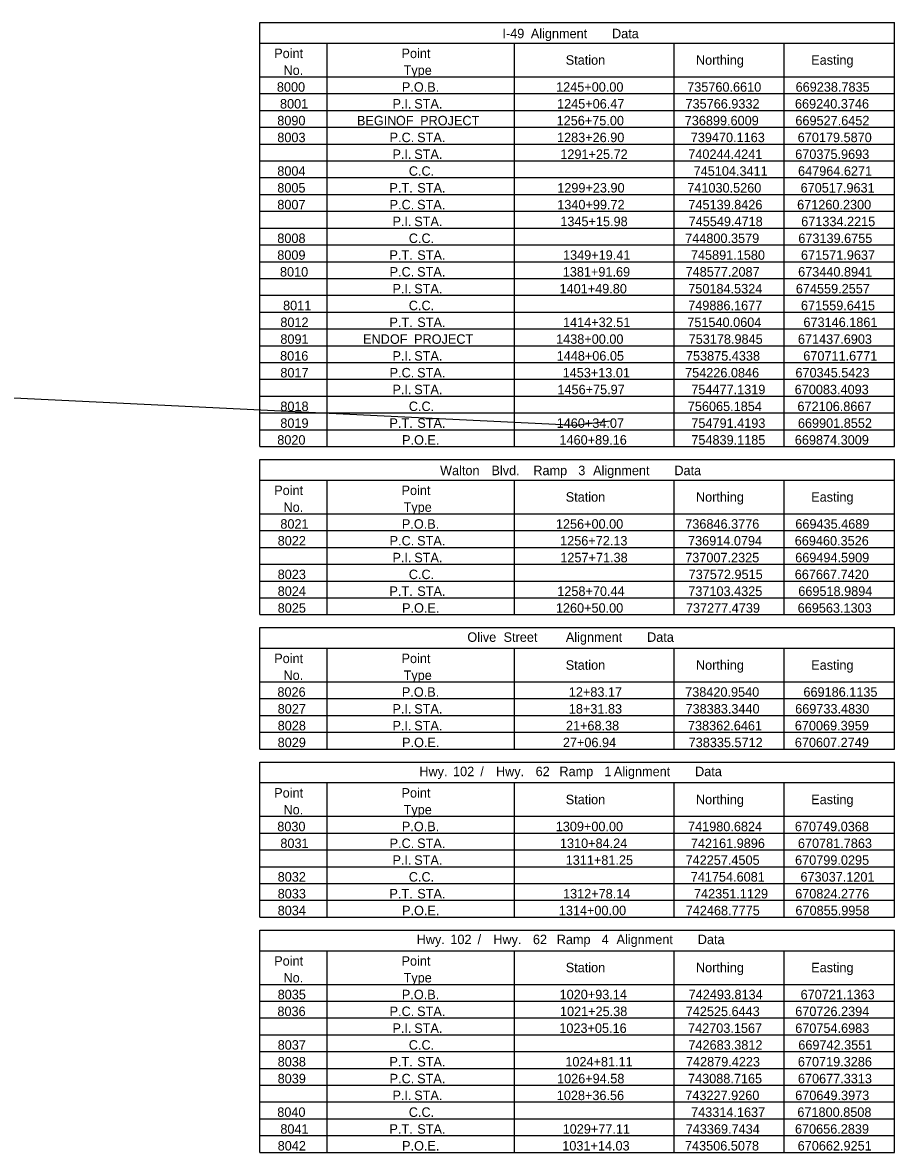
# Model space of a CAD drawing. Extents: x 672566 to 676329, y 739687 to 740710.
# Drawn here: x 673612 to 674071, y 739910 to 740505 of the extents above; entities that cross this region are included whole.
import ezdxf

# ---------------------------------------------------------------- set-up
doc = ezdxf.new("R2010")
doc.units = 0
doc.layers.add('R_Border', color=7, linetype='Continuous')
doc.layers.add('S_BASELINE', color=7, linetype='Continuous')

msp = doc.modelspace()

# ---------------------------------------------------------------- linework, layer by layer
at = {"layer": 'R_Border'}
msp.add_lwpolyline([(673921.66, 740294.96), (673903.74, 740292.61), (672625.13, 740354.75)], dxfattribs=at)
at = {"layer": 'S_BASELINE'}
for p, q in [((673737.18, 740504.83), (674071.38, 740504.83)), ((673737.18, 740281.51), (673737.18, 740504.83)), ((674071.38, 740281.51), (674071.38, 740504.83)), ((673737.18, 740502.83), (673737.18, 740502.83)), ((673737.18, 740493.98), (674071.38, 740493.98)), ((673772.59, 740281.51), (673772.59, 740493.98)), ((673871.3, 740281.51), (673871.3, 740493.98)), ((673955.4, 740281.51), (673955.4, 740493.98)), ((674013.39, 740281.51), (674013.39, 740493.98)), ((673737.18, 740476.27), (674071.38, 740476.27)), ((673737.18, 740476.27), (673772.59, 740476.27)), ((673737.18, 740467.42), (674071.38, 740467.42)), ((673737.18, 740458.57), (674071.38, 740458.57)), ((673737.18, 740449.72), (674071.38, 740449.72)), ((673737.18, 740440.86), (674071.38, 740440.86)), ((673737.18, 740432.01), (674071.38, 740432.01)), ((673737.18, 740423.16), (674071.38, 740423.16)), ((673737.18, 740414.3), (674071.38, 740414.3)), ((673737.18, 740405.45), (674071.38, 740405.45)), ((673737.18, 740396.6), (674071.38, 740396.6)), ((673737.18, 740387.74), (674071.38, 740387.74)), ((673737.18, 740378.89), (674071.38, 740378.89)), ((673737.18, 740370.04), (674071.38, 740370.04)), ((673737.18, 740361.19), (674071.38, 740361.19)), ((673737.18, 740352.33), (674071.38, 740352.33)), ((673737.18, 740343.48), (674071.38, 740343.48)), ((673737.18, 740334.63), (674071.38, 740334.63)), ((673737.18, 740325.77), (674071.38, 740325.77)), ((673737.18, 740316.92), (674071.38, 740316.92)), ((673737.18, 740308.07), (674071.38, 740308.07)), ((673737.18, 740299.21), (674071.38, 740299.21)), ((673737.18, 740290.36), (674071.38, 740290.36)), ((673737.18, 740281.51), (674071.38, 740281.51)), ((673737.18, 740274.66), (674071.38, 740274.66)), ((673737.18, 740192.98), (673737.18, 740274.66)), ((674071.38, 740192.98), (674071.38, 740274.66)), ((673737.18, 740263.8), (674071.38, 740263.8)), ((673772.59, 740192.98), (673772.59, 740263.8)), ((673871.3, 740192.98), (673871.3, 740263.8)), ((673955.4, 740192.98), (673955.4, 740263.8)), ((674013.39, 740192.98), (674013.39, 740263.8)), ((673737.18, 740246.1), (674071.38, 740246.1)), ((673737.18, 740246.1), (673772.59, 740246.1)), ((673737.18, 740237.24), (674071.38, 740237.24)), ((673737.18, 740228.39), (674071.38, 740228.39)), ((673737.18, 740219.54), (674071.38, 740219.54)), ((673737.18, 740210.68), (674071.38, 740210.68)), ((673737.18, 740201.83), (674071.38, 740201.83)), ((673737.18, 740192.98), (674071.38, 740192.98)), ((673737.18, 740186.13), (674071.38, 740186.13)), ((673737.18, 740122.15), (673737.18, 740186.13)), ((674071.38, 740122.15), (674071.38, 740186.13)), ((673737.18, 740175.27), (674071.38, 740175.27)), ((673772.59, 740122.15), (673772.59, 740175.27)), ((673871.3, 740122.15), (673871.3, 740175.27)), ((673955.4, 740122.15), (673955.4, 740175.27)), ((674013.39, 740122.15), (674013.39, 740175.27)), ((673737.18, 740157.57), (674071.38, 740157.57)), ((673737.18, 740157.57), (673772.59, 740157.57)), ((673737.18, 740148.71), (674071.38, 740148.71)), ((673737.18, 740139.86), (674071.38, 740139.86)), ((673737.18, 740131.01), (674071.38, 740131.01)), ((673737.18, 740122.15), (674071.38, 740122.15)), ((673737.18, 740115.3), (674071.38, 740115.3)), ((673737.18, 740033.62), (673737.18, 740115.3)), ((674071.38, 740033.62), (674071.38, 740115.3)), ((673737.18, 740104.45), (674071.38, 740104.45)), ((673772.59, 740033.62), (673772.59, 740104.45)), ((673871.3, 740033.62), (673871.3, 740104.45)), ((673955.4, 740033.62), (673955.4, 740104.45)), ((674013.39, 740033.62), (674013.39, 740104.45)), ((673737.18, 740086.74), (674071.38, 740086.74)), ((673737.18, 740086.74), (673772.59, 740086.74)), ((673737.18, 740077.89), (674071.38, 740077.89)), ((673737.18, 740069.04), (674071.38, 740069.04)), ((673737.18, 740060.18), (674071.38, 740060.18)), ((673737.18, 740051.33), (674071.38, 740051.33)), ((673737.18, 740042.48), (674071.38, 740042.48)), ((673737.18, 740033.62), (674071.38, 740033.62)), ((673737.18, 740026.77), (674071.38, 740026.77)), ((673737.18, 739909.68), (673737.18, 740026.77)), ((673737.18, 740024.77), (673737.18, 740024.77)), ((674071.38, 739909.68), (674071.38, 740026.77)), ((673737.18, 740015.92), (674071.38, 740015.92)), ((673772.59, 739909.68), (673772.59, 740015.92)), ((673871.3, 739909.68), (673871.3, 740015.92)), ((673955.4, 739909.68), (673955.4, 740015.92)), ((674013.39, 739909.68), (674013.39, 740015.92)), ((673737.18, 739998.21), (674071.38, 739998.21)), ((673737.18, 739998.21), (673772.59, 739998.21)), ((673737.18, 739989.36), (674071.38, 739989.36)), ((673737.18, 739980.51), (674071.38, 739980.51)), ((673737.18, 739971.65), (674071.38, 739971.65)), ((673737.18, 739962.8), (674071.38, 739962.8)), ((673737.18, 739953.95), (674071.38, 739953.95)), ((673737.18, 739945.09), (674071.38, 739945.09)), ((673737.18, 739936.24), (674071.38, 739936.24)), ((673737.18, 739927.39), (674071.38, 739927.39)), ((673737.18, 739918.54), (674071.38, 739918.54)), ((673737.18, 739909.68), (674071.38, 739909.68))]:
    msp.add_line(p, q, dxfattribs=at)

# ---------------------------------------------------------------- texts
for s, p in [('I-49', (673864.92, 740496.59)), (' Alignment', (673878.01, 740496.59)), (' Data', (673920.79, 740496.59)), ('Point', (673744.72, 740486.13)), ('Point', (673811.78, 740486.13)), ('Station', (673898.27, 740482.63)), ('Northing', (673966.86, 740482.63)), ('Easting', (674027.56, 740482.63)), ('No.', (673749.61, 740477.27)), ('Type', (673812.86, 740477.27)), ('8000', (673746.13, 740468.42)), ('P.O.B.', (673811.96, 740468.42)), ('1245+00.00', (673893.2, 740468.42)), ('735760.6610', (673962.24, 740468.42)), ('669238.7835', (674019.34, 740468.42)), ('8001', (673747.77, 740459.57)), ('P.I.', (673807.02, 740459.57)), (' STA.', (673816.62, 740459.57)), ('1245+06.47', (673893.69, 740459.57)), ('735766.9332', (673961.35, 740459.57)), ('669240.3746', (674019.01, 740459.57)), ('8090', (673746.33, 740450.71)), ('BEGIN', (673788.3, 740450.71)), (' OF', (673806.98, 740450.71)), (' PROJECT', (673819.72, 740450.71)), ('1256+75.00', (673893.47, 740450.71)), ('736899.6009', (673960.94, 740450.71)), ('669527.6452', (674019.22, 740450.71)), ('8003', (673746.35, 740441.86)), ('P.C.', (673805.49, 740441.86)), (' STA.', (673818.15, 740441.86)), ('1283+26.90', (673893.67, 740441.86)), ('739470.1163', (673964.11, 740441.86)), ('670179.5870', (674020.46, 740441.86)), ('P.I.', (673807.02, 740433.01)), (' STA.', (673816.62, 740433.01)), ('1291+25.72', (673895.42, 740433.01)), ('740244.4241', (673962.81, 740433.01)), ('670375.9693', (674019.14, 740433.01)), ('8004', (673746.35, 740424.15)), ('C.C.', (673815.61, 740424.15)), ('745104.3411', (673965.64, 740424.15)), ('647964.6271', (674020.64, 740424.15)), ('8005', (673746.35, 740415.3)), ('P.T.', (673805.41, 740415.3)), (' STA.', (673818.23, 740415.3)), ('1299+23.90', (673893.79, 740415.3)), ('741030.5260', (673962.28, 740415.3)), ('670517.9631', (674021.98, 740415.3)), ('8007', (673746.35, 740406.45)), ('P.C.', (673805.49, 740406.45)), (' STA.', (673818.15, 740406.45)), ('1340+99.72', (673893.81, 740406.45)), ('745139.8426', (673962.87, 740406.45)), ('671260.2300', (674020.15, 740406.45)), ('P.I.', (673807.02, 740397.6)), (' STA.', (673816.62, 740397.6)), ('1345+15.98', (673895.42, 740397.6)), ('745549.4718', (673963.01, 740397.6)), ('671334.2215', (674022.29, 740397.6)), ('8008', (673746.35, 740388.74)), ('C.C.', (673815.61, 740388.74)), ('744800.3579', (673961.18, 740388.74)), ('673139.6755', (674020.76, 740388.74)), ('8009', (673746.33, 740379.89)), ('P.T.', (673805.41, 740379.89)), (' STA.', (673818.23, 740379.89)), ('1349+19.41', (673896.84, 740379.89)), ('745891.1580', (673964.2, 740379.89)), ('671571.9637', (674022.17, 740379.89)), ('8010', (673747.75, 740371.04)), ('P.C.', (673805.49, 740371.04)), (' STA.', (673818.15, 740371.04)), ('1381+91.69', (673896.7, 740371.04)), ('748577.2087', (673961.39, 740371.04)), ('673440.8941', (674020.68, 740371.04)), ('P.I.', (673807.02, 740362.18)), (' STA.', (673816.62, 740362.18)), ('1401+49.80', (673895.01, 740362.18)), ('750184.5324', (673962.81, 740362.18)), ('674559.2557', (674019.46, 740362.18)), ('8011', (673749.38, 740353.33)), ('C.C.', (673815.61, 740353.33)), ('749886.1677', (673962.77, 740353.33)), ('671559.6415', (674022.17, 740353.33)), ('8012', (673747.96, 740344.48)), ('P.T.', (673805.41, 740344.48)), (' STA.', (673818.23, 740344.48)), ('1414+32.51', (673896.84, 740344.48)), ('751540.0604', (673962.3, 740344.48)), ('673146.1861', (674023.47, 740344.48)), ('8091', (673747.96, 740335.62)), ('END', (673791.49, 740335.62)), (' OF', (673803.8, 740335.62)), (' PROJECT', (673816.54, 740335.62)), ('1438+00.00', (673893.2, 740335.62)), ('753178.9845', (673963.01, 740335.62)), ('671437.6903', (674020.56, 740335.62)), ('8016', (673747.82, 740326.77)), ('P.I.', (673807.02, 740326.77)), (' STA.', (673816.62, 740326.77)), ('1448+06.05', (673893.49, 740326.77)), ('753875.4338', (673961.59, 740326.77)), ('670711.6771', (674023.39, 740326.77)), ('8017', (673747.96, 740317.92)), ('P.C.', (673805.49, 740317.92)), (' STA.', (673818.15, 740317.92)), ('1453+13.01', (673896.64, 740317.92)), ('754226.0846', (673961.14, 740317.92)), ('670345.5423', (674019.26, 740317.92)), ('P.I.', (673807.02, 740309.07)), (' STA.', (673816.62, 740309.07)), ('1456+75.97', (673893.89, 740309.07)), ('754477.1319', (673964.4, 740309.07)), ('670083.4093', (674018.87, 740309.07)), ('8018', (673747.96, 740300.21)), ('C.C.', (673815.61, 740300.21)), ('756065.1854', (673962.57, 740300.21)), ('672106.8667', (674020.32, 740300.21)), ('8019', (673747.94, 740291.36)), (' STA.', (673818.23, 740291.36)), ('1460+34.07', (673893.49, 740291.36)), ('754791.4193', (673964.42, 740291.36)), ('669901.8552', (674020.56, 740291.36)), ('P.T.', (673805.41, 740291.36)), ('8020', (673746.33, 740282.51)), ('P.O.E.', (673812.07, 740282.51)), ('1460+89.16', (673894.97, 740282.51)), ('754839.1185', (673964.42, 740282.51)), ('669874.3009', (674018.93, 740282.51)), ('Walton', (673832.08, 740266.42)), (' Blvd.', (673857.29, 740266.42)), (' Ramp', (673879.35, 740266.42)), (' 3', (673903.02, 740266.42)), (' Alignment', (673910.84, 740266.42)), (' Data', (673953.63, 740266.42)), ('Point', (673744.72, 740255.95)), ('Point', (673811.78, 740255.95)), ('Station', (673898.27, 740252.45)), ('Northing', (673966.86, 740252.45)), ('Easting', (674027.56, 740252.45)), ('No.', (673749.61, 740247.09)), ('Type', (673812.86, 740247.09)), ('8021', (673747.96, 740238.24)), ('P.O.B.', (673811.96, 740238.24)), ('1256+00.00', (673893.08, 740238.24)), ('736846.3776', (673961.22, 740238.24)), ('669435.4689', (674019.2, 740238.24)), ('8022', (673746.55, 740229.39)), ('P.C.', (673805.49, 740229.39)), (' STA.', (673818.15, 740229.39)), ('1256+72.13', (673895.3, 740229.39)), ('736914.0794', (673962.69, 740229.39)), ('669460.3526', (674018.89, 740229.39)), ('P.I.', (673807.02, 740220.54)), (' STA.', (673816.62, 740220.54)), ('1257+71.38', (673895.42, 740220.54)), ('737007.2325', (673961.2, 740220.54)), ('669494.5909', (674019.12, 740220.54)), ('8023', (673746.55, 740211.68)), ('C.C.', (673815.61, 740211.68)), ('737572.9515', (673963.01, 740211.68)), ('667667.7420', (674018.89, 740211.68)), ('8024', (673746.55, 740202.83)), ('P.T.', (673805.41, 740202.83)), (' STA.', (673818.23, 740202.83)), ('1258+70.44', (673893.81, 740202.83)), ('737103.4325', (673962.81, 740202.83)), ('669518.9894', (674020.76, 740202.83)), ('8025', (673746.55, 740193.98)), ('P.O.E.', (673812.07, 740193.98)), ('1260+50.00', (673893.08, 740193.98)), ('737277.4739', (673961.57, 740193.98)), ('669563.1303', (674020.44, 740193.98)), ('Olive', (673846.45, 740178.63)), (' Street', (673863.68, 740178.63)), (' Alignment', (673896.47, 740178.63)), (' Data', (673939.25, 740178.63)), ('Point', (673744.72, 740167.42)), ('Point', (673811.78, 740167.42)), ('Station', (673898.27, 740163.92)), ('Northing', (673966.86, 740163.92)), ('Easting', (674027.56, 740163.92)), ('No.', (673749.61, 740158.56)), ('Type', (673812.86, 740158.56)), ('8026', (673746.41, 740149.71)), ('P.O.B.', (673811.96, 740149.71)), ('12+83.17', (673899.9, 740149.71)), ('738420.9540', (673961.18, 740149.71)), ('669186.1135', (674023.47, 740149.71)), ('8027', (673746.55, 740140.86)), ('P.I.', (673807.02, 740140.86)), (' STA.', (673816.62, 740140.86)), ('18+31.83', (673899.9, 740140.86)), ('738383.3440', (673961.37, 740140.86)), ('669733.4830', (674019.12, 740140.86)), ('8028', (673746.55, 740132.01)), ('P.I.', (673807.02, 740132.01)), (' STA.', (673816.62, 740132.01)), ('21+68.38', (673898.37, 740132.01)), ('738362.6461', (673962.65, 740132.01)), ('670069.3959', (674018.93, 740132.01)), ('8029', (673746.53, 740123.15)), ('P.O.E.', (673812.07, 740123.15)), ('27+06.94', (673896.76, 740123.15)), ('738335.5712', (673963.01, 740123.15)), ('670607.2749', (674018.93, 740123.15)), ('Hwy.', (673821.17, 740107.87)), (' 102', (673837.05, 740107.87)), (' /', (673851.41, 740107.87)), (' Hwy.', (673859.67, 740107.87)), (' 62', (673880.55, 740107.87)), (' Ramp', (673893.09, 740107.87)), (' 1', (673916.76, 740107.87)), (' Alignment', (673921.76, 740107.87)), (' Data', (673964.54, 740107.87)), ('Point', (673744.72, 740096.59)), ('Point', (673811.78, 740096.59)), ('Station', (673898.27, 740093.1)), ('Northing', (673966.86, 740093.1)), ('Easting', (674027.56, 740093.1)), ('No.', (673749.61, 740087.74)), ('Type', (673812.86, 740087.74)), ('8030', (673746.33, 740078.89)), ('P.O.B.', (673811.96, 740078.89)), ('1309+00.00', (673893, 740078.89)), ('741980.6824', (673962.69, 740078.89)), ('670749.0368', (674018.95, 740078.89)), ('8031', (673747.96, 740070.03)), ('P.C.', (673805.49, 740070.03)), (' STA.', (673818.15, 740070.03)), ('1310+84.24', (673895.22, 740070.03)), ('742161.9896', (673964.17, 740070.03)), ('670781.7863', (674020.56, 740070.03)), ('P.I.', (673807.02, 740061.18)), (' STA.', (673816.62, 740061.18)), ('1311+81.25', (673898.25, 740061.18)), ('742257.4505', (673961.39, 740061.18)), ('670799.0295', (674019.07, 740061.18)), ('8032', (673746.55, 740052.33)), ('C.C.', (673815.61, 740052.33)), ('741754.6081', (673964.11, 740052.33)), ('673037.1201', (674021.9, 740052.33)), ('8033', (673746.55, 740043.48)), ('P.T.', (673805.41, 740043.48)), (' STA.', (673818.23, 740043.48)), ('1312+78.14', (673896.84, 740043.48)), ('742351.1129', (673965.82, 740043.48)), ('670824.2776', (674019.12, 740043.48)), ('8034', (673746.55, 740034.62)), ('P.O.E.', (673812.07, 740034.62)), ('1314+00.00', (673894.61, 740034.62)), ('742468.7775', (673961.47, 740034.62)), ('670855.9958', (674019.26, 740034.62)), ('Hwy.', (673819.75, 740019.39)), (' 102', (673835.64, 740019.39)), (' /', (673849.99, 740019.39)), (' Hwy.', (673858.25, 740019.39)), (' 62', (673879.13, 740019.39)), (' Ramp', (673891.67, 740019.39)), (' 4', (673915.35, 740019.39)), (' Alignment', (673923.17, 740019.39)), (' Data', (673965.96, 740019.39)), ('Point', (673744.72, 740008.06)), ('Point', (673811.78, 740008.06)), ('Station', (673898.27, 740004.57)), ('Northing', (673966.86, 740004.57)), ('Easting', (674027.56, 740004.57)), ('No.', (673749.61, 739999.21)), ('Type', (673812.86, 739999.21)), ('8035', (673746.55, 739990.36)), ('P.O.B.', (673811.96, 739990.36)), ('1020+93.14', (673895.03, 739990.36)), ('742493.8134', (673963.01, 739990.36)), ('670721.1363', (674021.98, 739990.36)), ('8036', (673746.41, 739981.5)), ('P.C.', (673805.49, 739981.5)), (' STA.', (673818.15, 739981.5)), ('1021+25.38', (673895.22, 739981.5)), ('742525.6443', (673961.47, 739981.5)), ('670726.2394', (674019.14, 739981.5)), ('P.I.', (673807.02, 739972.65)), (' STA.', (673816.62, 739972.65)), ('1023+05.16', (673894.89, 739972.65)), ('742703.1567', (673962.69, 739972.65)), ('670754.6983', (674019.14, 739972.65)), ('8037', (673746.55, 739963.8)), ('C.C.', (673815.61, 739963.8)), ('742683.3812', (673962.89, 739963.8)), ('669742.3551', (674020.76, 739963.8)), ('8038', (673746.55, 739954.95)), ('P.T.', (673805.41, 739954.95)), (' STA.', (673818.23, 739954.95)), ('1024+81.11', (673898.06, 739954.95)), ('742879.4223', (673961.59, 739954.95)), ('670719.3286', (674020.54, 739954.95)), ('8039', (673746.53, 739946.09)), ('P.C.', (673805.49, 739946.09)), (' STA.', (673818.15, 739946.09)), ('1026+94.58', (673893.69, 739946.09)), ('743088.7165', (673962.69, 739946.09)), ('670677.3313', (674020.56, 739946.09)), ('P.I.', (673807.02, 739937.24)), (' STA.', (673816.62, 739937.24)), ('1028+36.56', (673893.55, 739937.24)), ('743227.9260', (673961.26, 739937.24)), ('670649.3973', (674019.14, 739937.24)), ('8040', (673746.33, 739928.39)), ('C.C.', (673815.61, 739928.39)), ('743314.1637', (673964.3, 739928.39)), ('671800.8508', (674020.28, 739928.39)), ('8041', (673747.96, 739919.53)), ('P.T.', (673805.41, 739919.53)), (' STA.', (673818.23, 739919.53)), ('1029+77.11', (673896.64, 739919.53)), ('743369.7434', (673961.47, 739919.53)), ('670656.2839', (674019.01, 739919.53)), ('8042', (673746.55, 739910.68)), ('P.O.E.', (673812.07, 739910.68)), ('1031+14.03', (673896.44, 739910.68)), ('743506.5078', (673961.08, 739910.68)), ('670662.9251', (674020.44, 739910.68))]:
    msp.add_text(s, height=4.994, dxfattribs=at).set_placement(p)

doc.saveas('drawing.dxf')
